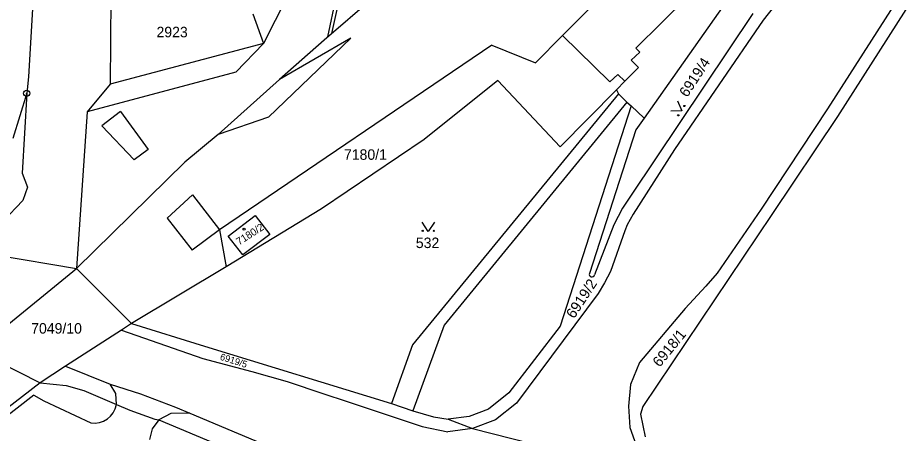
# Model space of a CAD drawing. Extents: x -593183 to -588034, y -1130415 to -1124994.
# Drawn here: x -591581.8 to -591438.4, y -1128430.1 to -1128362.8 of the extents above; entities that cross this region are included whole.
import ezdxf

# ---------------------------------------------------------------- set-up
doc = ezdxf.new("R2010")
doc.units = 0
for name, color, linetype in [('Vrstva 1', 7, 'Continuous'), ('Vrstva 18', 7, 'Continuous'), ('Vrstva 19', 7, 'Continuous'), ('Vrstva 24', 7, 'Continuous'), ('Vrstva 25', 7, 'Continuous'), ('Vrstva 27', 7, 'Continuous'), ('Vrstva 4', 7, 'Continuous')]:
    doc.layers.add(name, color=color, linetype=linetype)

msp = doc.modelspace()

# ---------------------------------------------------------------- linework, layer by layer
at = {"layer": 'Vrstva 1'}
for p, q in [((-591472.09, -1128344.02), (-591493.54, -1128365.64)), ((-591578.67, -1128348.32), (-591580, -1128372.33)), ((-591465.02, -1128351.21), (-591481.69, -1128367.68)), ((-591535.53, -1128354.22), (-591542, -1128366.97)), ((-591566.71, -1128358.26), (-591566.79, -1128373.53)), ((-591438.2, -1128358.07), (-591450.68, -1128377.51)), ((-591524, -1128359.39), (-591532.17, -1128366.41)), ((-591466.67, -1128359.58), (-591480.36, -1128379.02)), ((-591436.62, -1128359.26), (-591449.06, -1128378.79)), ((-591459.25, -1128360.84), (-591461.05, -1128363.16)), ((-591543.69, -1128362.14), (-591542, -1128366.97)), ((-591462.77, -1128362.1), (-591482.44, -1128391.51)), ((-591461.05, -1128363.16), (-591475.41, -1128384.12)), ((-591493.54, -1128365.64), (-591497.93, -1128370.07)), ((-591493.54, -1128365.64), (-591485.91, -1128373.16)), ((-591542, -1128366.97), (-591566.79, -1128373.53)), ((-591505.03, -1128367.24), (-591549.11, -1128397.12)), ((-591532.17, -1128366.41), (-591539.36, -1128372.78)), ((-591505.03, -1128367.24), (-591497.93, -1128370.07)), ((-591481.02, -1128368.33), (-591482.44, -1128369.63)), ((-591481.69, -1128367.68), (-591481.02, -1128368.33)), ((-591482.44, -1128369.63), (-591481.25, -1128370.85)), ((-591481.25, -1128370.85), (-591483.45, -1128373.07)), ((-591580, -1128372.33), (-591580.31, -1128375.02)), ((-591539.36, -1128372.78), (-591549.33, -1128381.67)), ((-591504.03, -1128372.94), (-591515.99, -1128382.49)), ((-591504.03, -1128372.94), (-591493.92, -1128383.71)), ((-591484.61, -1128371.95), (-591485.91, -1128373.16)), ((-591483.45, -1128373.07), (-591484.83, -1128374.45)), ((-591484.61, -1128371.95), (-591483.45, -1128373.07)), ((-591566.79, -1128373.53), (-591570.52, -1128378.03)), ((-591484.83, -1128374.45), (-591493.92, -1128383.71)), ((-591484.83, -1128374.45), (-591484.5, -1128375.1)), ((-591580.31, -1128375.02), (-591582.57, -1128382.36)), ((-591580.31, -1128375.02), (-591581.05, -1128387.98)), ((-591484.5, -1128375.1), (-591483.13, -1128376.43)), ((-591482.43, -1128377.06), (-591493.97, -1128412.77)), ((-591483.13, -1128376.43), (-591482.43, -1128377.06)), ((-591482.43, -1128377.06), (-591480.36, -1128379.02)), ((-591450.68, -1128377.51), (-591461.41, -1128393.8)), ((-591570.52, -1128378.03), (-591572.24, -1128403.38)), ((-591449.06, -1128378.79), (-591459.69, -1128394.63)), ((-591480.36, -1128379.02), (-591481.71, -1128380.94)), ((-591549.33, -1128381.67), (-591554.7, -1128386.19)), ((-591481.71, -1128380.94), (-591489.21, -1128404.19)), ((-591515.99, -1128382.49), (-591532.56, -1128393.74)), ((-591475.41, -1128384.12), (-591482.11, -1128394.58)), ((-591554.7, -1128386.19), (-591572.24, -1128403.38)), ((-591581.05, -1128387.98), (-591580.19, -1128390.21)), ((-591580.19, -1128390.21), (-591580.95, -1128392.41)), ((-591482.44, -1128391.51), (-591483.85, -1128393.62)), ((-591580.95, -1128392.41), (-591584.15, -1128395.73)), ((-591532.56, -1128393.74), (-591548.03, -1128403.11)), ((-591483.85, -1128393.62), (-591485.25, -1128396.33)), ((-591482.11, -1128394.58), (-591483.07, -1128396.33)), ((-591459.69, -1128394.63), (-591480.57, -1128425.75)), ((-591461.41, -1128393.8), (-591468.53, -1128404.17)), ((-591547.71, -1128398.17), (-591543.34, -1128394.82)), ((-591543.34, -1128394.82), (-591540.97, -1128397.92)), ((-591549.11, -1128397.12), (-591548.03, -1128403.11)), ((-591485.25, -1128396.33), (-591488.37, -1128404.45)), ((-591483.49, -1128397.28), (-591485.78, -1128403.87)), ((-591483.07, -1128396.33), (-591483.49, -1128397.28)), ((-591545.31, -1128401.21), (-591547.71, -1128398.17)), ((-591540.97, -1128397.92), (-591545.31, -1128401.21)), ((-591592.97, -1128399.9), (-591572.24, -1128403.38)), ((-591548.03, -1128403.11), (-591563.34, -1128412.33)), ((-591585.04, -1128413.8), (-591572.24, -1128403.38)), ((-591572.24, -1128403.38), (-591563.34, -1128412.33)), ((-591485.78, -1128403.87), (-591486.77, -1128405.7)), ((-591468.53, -1128404.17), (-591470.34, -1128406.24)), ((-591486.77, -1128405.7), (-591487.8, -1128407.48)), ((-591470.34, -1128406.24), (-591473.68, -1128409.9)), ((-591487.8, -1128407.48), (-591501.02, -1128425.23)), ((-591473.68, -1128409.9), (-591481.11, -1128418.63)), ((-591564.96, -1128413.38), (-591574.01, -1128419.24)), ((-591563.34, -1128412.33), (-591564.96, -1128413.38)), ((-591564.96, -1128413.38), (-591551.81, -1128417.99)), ((-591563.34, -1128412.33), (-591551.52, -1128415.98)), ((-591493.97, -1128412.77), (-591502.25, -1128423.56)), ((-591551.52, -1128415.98), (-591521.27, -1128425.3)), ((-591588.5, -1128416.71), (-591578.14, -1128421.92)), ((-591551.81, -1128417.99), (-591543.89, -1128420.09)), ((-591481.11, -1128418.63), (-591482.58, -1128422.18)), ((-591574.01, -1128419.24), (-591578.14, -1128421.92)), ((-591574.01, -1128419.24), (-591566.82, -1128422.12)), ((-591543.89, -1128420.09), (-591538.17, -1128421.7)), ((-591578.14, -1128421.92), (-591618.58, -1128453.23)), ((-591578.14, -1128421.92), (-591573.94, -1128422.34)), ((-591538.17, -1128421.7), (-591532.22, -1128423.73)), ((-591573.94, -1128422.34), (-591571.07, -1128423.15)), ((-591571.07, -1128423.15), (-591565.78, -1128425.43)), ((-591566.82, -1128422.12), (-591561.88, -1128423.69)), ((-591482.58, -1128422.18), (-591482.9, -1128425.69)), ((-591579.14, -1128423.95), (-591611.98, -1128449.26)), ((-591579.14, -1128423.95), (-591577.52, -1128424.84)), ((-591577.52, -1128424.84), (-591569.95, -1128428.42)), ((-591561.88, -1128423.69), (-591556.22, -1128425.85)), ((-591532.22, -1128423.73), (-591528.6, -1128424.89)), ((-591502.25, -1128423.56), (-591505.54, -1128426.18)), ((-591565.78, -1128425.43), (-591563.62, -1128426.36)), ((-591556.22, -1128425.85), (-591553.91, -1128426.82)), ((-591528.6, -1128424.89), (-591516.3, -1128429)), ((-591521.27, -1128425.3), (-591517.8, -1128426.45)), ((-591505.54, -1128426.18), (-591508.67, -1128427.4)), ((-591501.02, -1128425.23), (-591504.4, -1128427.91)), ((-591482.9, -1128425.69), (-591482.67, -1128429.16)), ((-591480.57, -1128425.75), (-591480.95, -1128426.98)), ((-591563.62, -1128426.36), (-591559.56, -1128427.81)), ((-591553.91, -1128426.82), (-591531.07, -1128436.42)), ((-591517.8, -1128426.45), (-591514.44, -1128427.44)), ((-591514.44, -1128427.44), (-591512.06, -1128427.81)), ((-591508.67, -1128427.4), (-591512.06, -1128427.81)), ((-591480.95, -1128426.98), (-591480.18, -1128430.69)), ((-591559.56, -1128427.81), (-591558.93, -1128427.93)), ((-591558.93, -1128427.93), (-591549.51, -1128431.84)), ((-591516.3, -1128429), (-591512.13, -1128429.86)), ((-591512.06, -1128427.81), (-591508.12, -1128429.34)), ((-591504.4, -1128427.91), (-591508.12, -1128429.34)), ((-591482.67, -1128429.16), (-591481.62, -1128432.05)), ((-591508.12, -1128429.34), (-591512.13, -1128429.86)), ((-591508.12, -1128429.34), (-591478.63, -1128436.77))]:
    msp.add_line(p, q, dxfattribs=at)
for centre, radius, start, end in [((-591488.79, -1128404.31), 0.44, 164.1749, 341.428), ((-591569.42, -1128424.75), 3.71, 261.8503, 349.4327)]:
    msp.add_arc(centre, radius, start, end, dxfattribs=at)
at = {"layer": 'Vrstva 24'}
for radius in [0.5, 0.0327]:
    msp.add_circle((-591580.31, -1128375.02), radius, dxfattribs=at)
at = {"layer": 'Vrstva 25'}
for points in [[(-591474.95, -1128376.22), (-591474.24, -1128377.88), (-591476.04, -1128377.9)], [(-591514.3, -1128395.89), (-591515.3, -1128397.39), (-591516.3, -1128395.89)]]:
    msp.add_lwpolyline(points, dxfattribs=at)
for centre, radius in [((-591473.83, -1128377.07), 0.1), ((-591474.82, -1128378.58), 0.1), ((-591545.12, -1128397.02), 0.175), ((-591545.12, -1128397.02), 0.15), ((-591516.2, -1128397.29), 0.1), ((-591514.4, -1128397.29), 0.1)]:
    msp.add_circle(centre, radius, dxfattribs=at)
at = {"layer": 'Vrstva 27'}
for p, q in [((-591531.57, -1128365.89), (-591524.38, -1128331.78)), ((-591523.78, -1128332.01), (-591530.94, -1128365.35)), ((-591530.94, -1128365.35), (-591531.57, -1128365.89))]:
    msp.add_line(p, q, dxfattribs=at)
at = {"layer": 'Vrstva 4'}
for p, q in [((-591527.84, -1128366.06), (-591541.14, -1128378.9)), ((-591527.84, -1128366.06), (-591539.36, -1128372.78)), ((-591542, -1128366.97), (-591546.43, -1128371.58)), ((-591546.43, -1128371.58), (-591570.52, -1128378.03)), ((-591484.5, -1128375.1), (-591517.86, -1128415.78)), ((-591483.13, -1128376.43), (-591512.75, -1128412.59)), ((-591565.12, -1128377.94), (-591568.17, -1128380.3)), ((-591565.12, -1128377.94), (-591560.63, -1128384.1)), ((-591541.14, -1128378.9), (-591549.33, -1128381.67)), ((-591568.17, -1128380.3), (-591562.92, -1128385.78)), ((-591560.63, -1128384.1), (-591562.92, -1128385.78)), ((-591553.47, -1128391.46), (-591557.55, -1128395.24)), ((-591553.47, -1128391.46), (-591549.11, -1128397.12)), ((-591557.55, -1128395.24), (-591553.52, -1128400.45)), ((-591549.11, -1128397.12), (-591553.52, -1128400.45)), ((-591512.75, -1128412.59), (-591517.8, -1128426.45)), ((-591517.86, -1128415.78), (-591521.27, -1128425.3)), ((-591565.89, -1128423.65), (-591566.82, -1128422.12)), ((-591565.78, -1128425.43), (-591565.89, -1128423.65)), ((-591557, -1128426.89), (-591558.93, -1128427.93)), ((-591553.91, -1128426.82), (-591557, -1128426.89)), ((-591558.93, -1128427.93), (-591560, -1128429.36)), ((-591560, -1128429.36), (-591560.46, -1128431.09))]:
    msp.add_line(p, q, dxfattribs=at)

# ---------------------------------------------------------------- texts
at = {"layer": 'Vrstva 18'}
for s, p in [('2923', (-591559.3, -1128365.94)), ('7180/1', (-591528.95, -1128385.79)), ('532', (-591517.31, -1128400.09)), ('7049/10', (-591579.59, -1128413.95))]:
    msp.add_text(s, height=1.7, dxfattribs=at).set_placement(p)
for s, height, rotation, p in [('6919/4', 1.7, 56.8421, (-591473.37, -1128375.78)), ('6919/2', 1.7, 56.8421, (-591491.69, -1128411.64)), ('6918/1', 1.7, 50.7992, (-591477.82, -1128419.5)), ('6919/5', 1.1, 342.512, (-591549.11, -1128418.17))]:
    msp.add_text(s, height=height, rotation=rotation, dxfattribs=at).set_placement(p)
at = {"layer": 'Vrstva 19'}
msp.add_text('7180/2', height=1.2, rotation=32.6003, dxfattribs=at).set_placement((-591545.92, -1128399.67))

doc.saveas('drawing.dxf')
